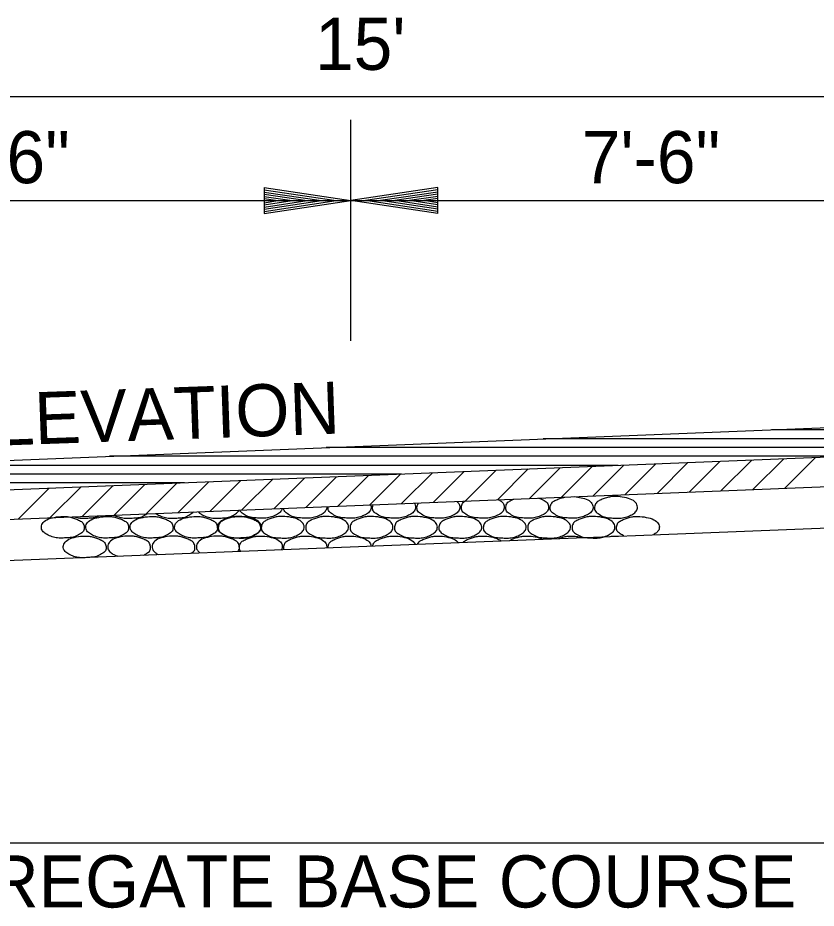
# Model space of a CAD drawing. Extents: x 1955768 to 1955917, y 566446 to 566546.
# Drawn here: x 1955835.83 to 1955845.04, y 566460.98 to 566471.25 of the extents above; entities that cross this region are included whole.
import ezdxf

# ---------------------------------------------------------------- set-up
doc = ezdxf.new("R2010")
doc.units = 0
doc.layers.add('R_Border', color=7, linetype='Continuous')
doc.layers.add('R_Grid', color=7, linetype='Continuous')

msp = doc.modelspace()

# ---------------------------------------------------------------- linework, layer by layer
at = {"layer": 'R_Border'}
for p, q in [((1955826.173, 566465.764), (1955847.173, 566466.604)), ((1955826.087, 566465.42), (1955847.339, 566466.271)), ((1955831.826, 566465.309), (1955847.506, 566465.937)), ((1955820.673, 566464.389), (1955847.173, 566465.449))]:
    msp.add_line(p, q, dxfattribs=at)
at = {"layer": 'R_Grid'}
for p, q in [((1955847.173, 566470.336), (1955832.173, 566470.336)), ((1955839.673, 566467.522), (1955839.673, 566470.069)), ((1955838.671, 566469.289), (1955839.671, 566469.139)), ((1955838.671, 566469.289), (1955838.671, 566468.989)), ((1955838.671, 566469.264), (1955839.504, 566469.139)), ((1955838.671, 566469.238), (1955839.332, 566469.139)), ((1955840.673, 566469.289), (1955839.673, 566469.139)), ((1955840.673, 566469.264), (1955839.84, 566469.139)), ((1955840.673, 566469.238), (1955840.012, 566469.139)), ((1955840.673, 566468.989), (1955840.673, 566469.289)), ((1955832.173, 566469.139), (1955839.673, 566469.139)), ((1955838.671, 566469.213), (1955839.166, 566469.139)), ((1955838.671, 566469.187), (1955838.996, 566469.139)), ((1955838.671, 566469.162), (1955838.829, 566469.139)), ((1955838.671, 566468.989), (1955839.671, 566469.139)), ((1955838.671, 566469.09), (1955838.996, 566469.139)), ((1955838.671, 566469.039), (1955839.332, 566469.139)), ((1955838.671, 566469.014), (1955839.504, 566469.139)), ((1955838.671, 566469.064), (1955839.166, 566469.139)), ((1955838.671, 566469.115), (1955838.829, 566469.139)), ((1955839.673, 566469.139), (1955847.173, 566469.139)), ((1955840.673, 566468.989), (1955839.673, 566469.139)), ((1955840.673, 566469.014), (1955839.84, 566469.139)), ((1955840.673, 566469.039), (1955840.012, 566469.139)), ((1955840.673, 566469.213), (1955840.178, 566469.139)), ((1955840.673, 566469.064), (1955840.178, 566469.139)), ((1955840.673, 566469.188), (1955840.348, 566469.139)), ((1955840.673, 566469.09), (1955840.348, 566469.139)), ((1955840.673, 566469.162), (1955840.515, 566469.139)), ((1955840.673, 566469.115), (1955840.515, 566469.139)), ((1955851.239, 566466.498), (1955844.523, 566466.498)), ((1955850.532, 566466.393), (1955841.888, 566466.393)), ((1955847.904, 566466.293), (1955839.388, 566466.293)), ((1955845.395, 566466.193), (1955836.888, 566466.193)), ((1955844.294, 566466.149), (1955843.94, 566465.794)), ((1955844.663, 566466.163), (1955844.308, 566465.809)), ((1955845.031, 566466.178), (1955844.677, 566465.824)), ((1955842.754, 566466.087), (1955834.247, 566466.087)), ((1955841.716, 566466.046), (1955841.362, 566465.691)), ((1955842.085, 566466.06), (1955841.73, 566465.706)), ((1955842.453, 566466.075), (1955842.099, 566465.721)), ((1955842.821, 566466.09), (1955842.467, 566465.736)), ((1955843.19, 566466.105), (1955842.835, 566465.75)), ((1955843.558, 566466.119), (1955843.204, 566465.765)), ((1955843.926, 566466.134), (1955843.572, 566465.78)), ((1955840.254, 566465.987), (1955831.747, 566465.987)), ((1955839.138, 566465.942), (1955838.784, 566465.588)), ((1955839.507, 566465.957), (1955839.152, 566465.603)), ((1955839.875, 566465.972), (1955839.521, 566465.618)), ((1955840.243, 566465.987), (1955839.889, 566465.632)), ((1955840.612, 566466.001), (1955840.257, 566465.647)), ((1955840.98, 566466.016), (1955840.626, 566465.662)), ((1955841.348, 566466.031), (1955840.994, 566465.677)), ((1955837.754, 566465.887), (1955829.247, 566465.887)), ((1955836.56, 566465.839), (1955836.206, 566465.485)), ((1955836.929, 566465.854), (1955836.574, 566465.5)), ((1955837.297, 566465.869), (1955836.943, 566465.515)), ((1955837.665, 566465.884), (1955837.311, 566465.529)), ((1955838.034, 566465.898), (1955837.679, 566465.544)), ((1955838.402, 566465.913), (1955838.048, 566465.559)), ((1955838.77, 566465.928), (1955838.416, 566465.574)), ((1955836.192, 566465.825), (1955835.838, 566465.47)), ((1955847.173, 566461.733), (1955832.173, 566461.733))]:
    msp.add_line(p, q, dxfattribs=at)
for points, degree in [([(1955842.256, 566465.727), (1955842.273, 566465.725), (1955842.328, 566465.716), (1955842.408, 566465.695), (1955842.459, 566465.648), (1955842.47, 566465.593), (1955842.446, 566465.549), (1955842.402, 566465.518), (1955842.342, 566465.493), (1955842.277, 566465.478), (1955842.211, 566465.478), (1955842.15, 566465.483), (1955842.082, 566465.488), (1955842.021, 566465.524), (1955841.972, 566465.556), (1955841.967, 566465.607), (1955841.984, 566465.658), (1955842.023, 566465.682), (1955842.071, 566465.703), (1955842.109, 566465.715), (1955842.134, 566465.721), (1955842.139, 566465.722)], 3), ([(1955842.731, 566465.728), (1955842.76, 566465.729), (1955842.827, 566465.72), (1955842.92, 566465.695), (1955842.971, 566465.648), (1955842.982, 566465.593), (1955842.958, 566465.549), (1955842.914, 566465.518), (1955842.854, 566465.493), (1955842.789, 566465.478), (1955842.723, 566465.478), (1955842.662, 566465.483), (1955842.594, 566465.488), (1955842.533, 566465.524), (1955842.484, 566465.556), (1955842.479, 566465.607), (1955842.496, 566465.658), (1955842.535, 566465.682), (1955842.583, 566465.703), (1955842.629, 566465.717), (1955842.68, 566465.729), (1955842.712, 566465.73), (1955842.731, 566465.728)], 3), ([(1955839.901, 566465.632), (1955839.904, 566465.623), (1955839.91, 566465.593), (1955839.886, 566465.549), (1955839.842, 566465.518), (1955839.782, 566465.493), (1955839.717, 566465.478), (1955839.651, 566465.478), (1955839.59, 566465.483), (1955839.522, 566465.488), (1955839.461, 566465.524), (1955839.412, 566465.556), (1955839.409, 566465.594), (1955839.411, 566465.609), (1955839.411, 566465.613)], 3), ([(1955840.401, 566465.653), (1955840.406, 566465.647), (1955840.414, 566465.632), (1955840.422, 566465.593), (1955840.398, 566465.549), (1955840.354, 566465.518), (1955840.294, 566465.493), (1955840.229, 566465.478), (1955840.163, 566465.478), (1955840.102, 566465.483), (1955840.034, 566465.488), (1955839.973, 566465.524), (1955839.924, 566465.556), (1955839.92, 566465.6), (1955839.925, 566465.624), (1955839.929, 566465.634)], 3), ([(1955840.894, 566465.672), (1955840.907, 566465.662), (1955840.924, 566465.642), (1955840.934, 566465.593), (1955840.91, 566465.549), (1955840.866, 566465.518), (1955840.806, 566465.493), (1955840.741, 566465.478), (1955840.675, 566465.478), (1955840.614, 566465.483), (1955840.546, 566465.488), (1955840.485, 566465.524), (1955840.436, 566465.556), (1955840.431, 566465.607), (1955840.442, 566465.64), (1955840.452, 566465.654), (1955840.453, 566465.655)], 3), ([(1955841.374, 566465.691), (1955841.379, 566465.689), (1955841.406, 566465.675), (1955841.435, 566465.648), (1955841.446, 566465.593), (1955841.422, 566465.549), (1955841.378, 566465.518), (1955841.318, 566465.493), (1955841.253, 566465.478), (1955841.187, 566465.478), (1955841.126, 566465.483), (1955841.058, 566465.488), (1955840.997, 566465.524), (1955840.948, 566465.556), (1955840.943, 566465.607), (1955840.958, 566465.653), (1955840.98, 566465.67), (1955840.991, 566465.676)], 3), ([(1955841.835, 566465.71), (1955841.859, 566465.703), (1955841.905, 566465.686), (1955841.947, 566465.648), (1955841.958, 566465.593), (1955841.934, 566465.549), (1955841.89, 566465.518), (1955841.83, 566465.493), (1955841.765, 566465.478), (1955841.699, 566465.478), (1955841.638, 566465.483), (1955841.57, 566465.488), (1955841.509, 566465.524), (1955841.46, 566465.556), (1955841.455, 566465.607), (1955841.472, 566465.658), (1955841.51, 566465.681), (1955841.538, 566465.694), (1955841.55, 566465.698)], 3), ([(1955836.942, 566465.514), (1955836.956, 566465.508), (1955836.997, 566465.491), (1955837.054, 566465.478), (1955837.121, 566465.478), (1955837.182, 566465.483), (1955837.25, 566465.488), (1955837.294, 566465.514), (1955837.315, 566465.527), (1955837.318, 566465.529)], 3), ([(1955837.421, 566465.533), (1955837.426, 566465.53), (1955837.449, 566465.515), (1955837.502, 566465.493), (1955837.566, 566465.478), (1955837.633, 566465.478), (1955837.694, 566465.483), (1955837.762, 566465.488), (1955837.816, 566465.52), (1955837.847, 566465.54), (1955837.857, 566465.551)], 3), ([(1955837.912, 566465.553), (1955837.914, 566465.551), (1955837.924, 566465.539), (1955837.954, 566465.518), (1955838.014, 566465.493), (1955838.078, 566465.478), (1955838.145, 566465.478), (1955838.206, 566465.483), (1955838.274, 566465.488), (1955838.335, 566465.524), (1955838.374, 566465.55), (1955838.382, 566465.571), (1955838.383, 566465.572)], 3), ([(1955838.88, 566465.592), (1955838.876, 566465.575), (1955838.859, 566465.547), (1955838.818, 566465.518), (1955838.758, 566465.493), (1955838.693, 566465.478), (1955838.627, 566465.478), (1955838.566, 566465.483), (1955838.498, 566465.488), (1955838.437, 566465.524), (1955838.398, 566465.55), (1955838.389, 566465.571), (1955838.389, 566465.572)], 3), ([(1955839.393, 566465.612), (1955839.394, 566465.609), (1955839.394, 566465.586), (1955839.374, 566465.549), (1955839.33, 566465.518), (1955839.27, 566465.493), (1955839.205, 566465.478), (1955839.139, 566465.478), (1955839.078, 566465.483), (1955839.01, 566465.488), (1955838.949, 566465.524), (1955838.903, 566465.554), (1955838.898, 566465.584), (1955838.898, 566465.592)], 3), ([(1955836.349, 566465.499), (1955836.319, 566465.499), (1955836.252, 566465.491), (1955836.159, 566465.465), (1955836.108, 566465.419), (1955836.097, 566465.364), (1955836.121, 566465.32), (1955836.166, 566465.289), (1955836.225, 566465.264), (1955836.29, 566465.248), (1955836.356, 566465.249), (1955836.417, 566465.254), (1955836.486, 566465.259), (1955836.546, 566465.295), (1955836.595, 566465.327), (1955836.6, 566465.378), (1955836.584, 566465.428), (1955836.545, 566465.452), (1955836.497, 566465.473), (1955836.45, 566465.488), (1955836.399, 566465.499), (1955836.367, 566465.501), (1955836.349, 566465.499)], 3), ([(1955836.477, 566465.496), (1955836.503, 566465.487), (1955836.544, 566465.478), (1955836.609, 566465.478), (1955836.67, 566465.483), (1955836.728, 566465.487), (1955836.76, 566465.502), (1955836.769, 566465.507)], 3), ([(1955836.861, 566465.499), (1955836.831, 566465.499), (1955836.764, 566465.491), (1955836.671, 566465.465), (1955836.62, 566465.419), (1955836.609, 566465.364), (1955836.633, 566465.32), (1955836.678, 566465.289), (1955836.737, 566465.264), (1955836.802, 566465.248), (1955836.868, 566465.249), (1955836.929, 566465.254), (1955836.998, 566465.259), (1955837.058, 566465.295), (1955837.107, 566465.327), (1955837.112, 566465.378), (1955837.096, 566465.428), (1955837.057, 566465.452), (1955837.009, 566465.473), (1955836.962, 566465.488), (1955836.911, 566465.499), (1955836.879, 566465.501), (1955836.861, 566465.499)], 3), ([(1955837.373, 566465.499), (1955837.343, 566465.499), (1955837.276, 566465.491), (1955837.183, 566465.465), (1955837.132, 566465.419), (1955837.121, 566465.364), (1955837.145, 566465.32), (1955837.19, 566465.289), (1955837.249, 566465.264), (1955837.314, 566465.248), (1955837.38, 566465.249), (1955837.441, 566465.254), (1955837.51, 566465.259), (1955837.57, 566465.295), (1955837.619, 566465.327), (1955837.624, 566465.378), (1955837.608, 566465.428), (1955837.569, 566465.452), (1955837.521, 566465.473), (1955837.474, 566465.488), (1955837.423, 566465.499), (1955837.391, 566465.501), (1955837.373, 566465.499)], 3), ([(1955837.885, 566465.499), (1955837.855, 566465.499), (1955837.788, 566465.491), (1955837.695, 566465.465), (1955837.644, 566465.419), (1955837.633, 566465.364), (1955837.657, 566465.32), (1955837.702, 566465.289), (1955837.761, 566465.264), (1955837.826, 566465.248), (1955837.892, 566465.249), (1955837.953, 566465.254), (1955838.022, 566465.259), (1955838.082, 566465.295), (1955838.131, 566465.327), (1955838.136, 566465.378), (1955838.12, 566465.428), (1955838.081, 566465.452), (1955838.033, 566465.473), (1955837.986, 566465.488), (1955837.935, 566465.499), (1955837.903, 566465.501), (1955837.885, 566465.499)], 3), ([(1955838.38, 566465.499), (1955838.351, 566465.499), (1955838.284, 566465.491), (1955838.191, 566465.465), (1955838.14, 566465.419), (1955838.129, 566465.364), (1955838.153, 566465.32), (1955838.197, 566465.289), (1955838.257, 566465.264), (1955838.322, 566465.248), (1955838.388, 566465.249), (1955838.449, 566465.254), (1955838.517, 566465.259), (1955838.578, 566465.295), (1955838.627, 566465.327), (1955838.632, 566465.378), (1955838.615, 566465.428), (1955838.576, 566465.452), (1955838.528, 566465.473), (1955838.482, 566465.488), (1955838.431, 566465.499), (1955838.399, 566465.501), (1955838.38, 566465.499)], 3), ([(1955838.391, 566465.499), (1955838.421, 566465.499), (1955838.488, 566465.491), (1955838.581, 566465.465), (1955838.632, 566465.419), (1955838.643, 566465.364), (1955838.619, 566465.32), (1955838.575, 566465.289), (1955838.515, 566465.264), (1955838.45, 566465.248), (1955838.384, 566465.249), (1955838.323, 566465.254), (1955838.254, 566465.259), (1955838.194, 566465.295), (1955838.145, 566465.327), (1955838.14, 566465.378), (1955838.157, 566465.428), (1955838.196, 566465.452), (1955838.243, 566465.473), (1955838.29, 566465.488), (1955838.341, 566465.499), (1955838.373, 566465.501), (1955838.391, 566465.499)], 3), ([(1955838.887, 566465.499), (1955838.916, 566465.499), (1955838.984, 566465.491), (1955839.076, 566465.465), (1955839.127, 566465.419), (1955839.139, 566465.364), (1955839.114, 566465.32), (1955839.07, 566465.289), (1955839.011, 566465.264), (1955838.946, 566465.248), (1955838.88, 566465.249), (1955838.819, 566465.254), (1955838.75, 566465.259), (1955838.689, 566465.295), (1955838.641, 566465.327), (1955838.636, 566465.378), (1955838.652, 566465.428), (1955838.691, 566465.452), (1955838.739, 566465.473), (1955838.785, 566465.488), (1955838.836, 566465.499), (1955838.869, 566465.501), (1955838.887, 566465.499)], 3), ([(1955839.399, 566465.499), (1955839.428, 566465.499), (1955839.496, 566465.491), (1955839.588, 566465.465), (1955839.639, 566465.419), (1955839.651, 566465.364), (1955839.626, 566465.32), (1955839.582, 566465.289), (1955839.523, 566465.264), (1955839.458, 566465.248), (1955839.392, 566465.249), (1955839.331, 566465.254), (1955839.262, 566465.259), (1955839.201, 566465.295), (1955839.153, 566465.327), (1955839.148, 566465.378), (1955839.164, 566465.428), (1955839.203, 566465.452), (1955839.251, 566465.473), (1955839.297, 566465.488), (1955839.348, 566465.499), (1955839.381, 566465.501), (1955839.399, 566465.499)], 3), ([(1955839.911, 566465.499), (1955839.94, 566465.499), (1955840.008, 566465.491), (1955840.1, 566465.465), (1955840.151, 566465.419), (1955840.163, 566465.364), (1955840.138, 566465.32), (1955840.094, 566465.289), (1955840.035, 566465.264), (1955839.97, 566465.248), (1955839.904, 566465.249), (1955839.843, 566465.254), (1955839.774, 566465.259), (1955839.713, 566465.295), (1955839.665, 566465.327), (1955839.66, 566465.378), (1955839.676, 566465.428), (1955839.715, 566465.452), (1955839.763, 566465.473), (1955839.809, 566465.488), (1955839.86, 566465.499), (1955839.893, 566465.501), (1955839.911, 566465.499)], 3), ([(1955840.423, 566465.499), (1955840.452, 566465.499), (1955840.52, 566465.491), (1955840.612, 566465.465), (1955840.663, 566465.419), (1955840.675, 566465.364), (1955840.65, 566465.32), (1955840.606, 566465.289), (1955840.547, 566465.264), (1955840.482, 566465.248), (1955840.416, 566465.249), (1955840.355, 566465.254), (1955840.286, 566465.259), (1955840.225, 566465.295), (1955840.177, 566465.327), (1955840.172, 566465.378), (1955840.188, 566465.428), (1955840.227, 566465.452), (1955840.275, 566465.473), (1955840.321, 566465.488), (1955840.372, 566465.499), (1955840.405, 566465.501), (1955840.423, 566465.499)], 3), ([(1955840.935, 566465.499), (1955840.964, 566465.499), (1955841.032, 566465.491), (1955841.124, 566465.465), (1955841.175, 566465.419), (1955841.187, 566465.364), (1955841.162, 566465.32), (1955841.118, 566465.289), (1955841.059, 566465.264), (1955840.994, 566465.248), (1955840.928, 566465.249), (1955840.867, 566465.254), (1955840.798, 566465.259), (1955840.737, 566465.295), (1955840.689, 566465.327), (1955840.684, 566465.378), (1955840.7, 566465.428), (1955840.739, 566465.452), (1955840.787, 566465.473), (1955840.833, 566465.488), (1955840.884, 566465.499), (1955840.917, 566465.501), (1955840.935, 566465.499)], 3), ([(1955841.447, 566465.499), (1955841.476, 566465.499), (1955841.544, 566465.491), (1955841.636, 566465.465), (1955841.687, 566465.419), (1955841.699, 566465.364), (1955841.674, 566465.32), (1955841.63, 566465.289), (1955841.571, 566465.264), (1955841.506, 566465.248), (1955841.44, 566465.249), (1955841.379, 566465.254), (1955841.31, 566465.259), (1955841.249, 566465.295), (1955841.201, 566465.327), (1955841.196, 566465.378), (1955841.212, 566465.428), (1955841.251, 566465.452), (1955841.299, 566465.473), (1955841.345, 566465.488), (1955841.396, 566465.499), (1955841.429, 566465.501), (1955841.447, 566465.499)], 3), ([(1955841.959, 566465.499), (1955841.988, 566465.499), (1955842.056, 566465.491), (1955842.148, 566465.465), (1955842.199, 566465.419), (1955842.211, 566465.364), (1955842.186, 566465.32), (1955842.142, 566465.289), (1955842.083, 566465.264), (1955842.018, 566465.248), (1955841.952, 566465.249), (1955841.891, 566465.254), (1955841.822, 566465.259), (1955841.761, 566465.295), (1955841.713, 566465.327), (1955841.708, 566465.378), (1955841.724, 566465.428), (1955841.763, 566465.452), (1955841.811, 566465.473), (1955841.857, 566465.488), (1955841.908, 566465.499), (1955841.941, 566465.501), (1955841.959, 566465.499)], 3), ([(1955842.471, 566465.499), (1955842.5, 566465.499), (1955842.568, 566465.491), (1955842.66, 566465.465), (1955842.711, 566465.419), (1955842.723, 566465.364), (1955842.698, 566465.32), (1955842.654, 566465.289), (1955842.595, 566465.264), (1955842.53, 566465.248), (1955842.464, 566465.249), (1955842.403, 566465.254), (1955842.334, 566465.259), (1955842.273, 566465.295), (1955842.225, 566465.327), (1955842.22, 566465.378), (1955842.236, 566465.428), (1955842.275, 566465.452), (1955842.323, 566465.473), (1955842.369, 566465.488), (1955842.42, 566465.499), (1955842.453, 566465.501), (1955842.471, 566465.499)], 3), ([(1955842.821, 566465.275), (1955842.81, 566465.28), (1955842.778, 566465.299), (1955842.737, 566465.327), (1955842.732, 566465.378), (1955842.748, 566465.428), (1955842.787, 566465.452), (1955842.835, 566465.473), (1955842.881, 566465.488), (1955842.932, 566465.499), (1955842.965, 566465.501), (1955842.983, 566465.499)], 3), ([(1955842.983, 566465.499), (1955843.012, 566465.499), (1955843.08, 566465.491), (1955843.172, 566465.465), (1955843.223, 566465.419), (1955843.235, 566465.364), (1955843.21, 566465.32), (1955843.18, 566465.299), (1955843.165, 566465.291), (1955843.161, 566465.288)], 3), ([(1955836.601, 566465.273), (1955836.572, 566465.273), (1955836.504, 566465.264), (1955836.412, 566465.239), (1955836.361, 566465.193), (1955836.35, 566465.138), (1955836.374, 566465.093), (1955836.418, 566465.063), (1955836.478, 566465.037), (1955836.542, 566465.022), (1955836.609, 566465.023), (1955836.67, 566465.028), (1955836.738, 566465.033), (1955836.799, 566465.069), (1955836.848, 566465.101), (1955836.853, 566465.152), (1955836.836, 566465.202), (1955836.797, 566465.226), (1955836.749, 566465.247), (1955836.703, 566465.262), (1955836.652, 566465.273), (1955836.62, 566465.274), (1955836.601, 566465.273)], 3), ([(1955837.113, 566465.273), (1955837.084, 566465.273), (1955837.016, 566465.264), (1955836.924, 566465.239), (1955836.873, 566465.193), (1955836.862, 566465.138), (1955836.886, 566465.093), (1955836.93, 566465.063), (1955836.963, 566465.049), (1955836.984, 566465.041), (1955836.985, 566465.041)], 3), ([(1955837.285, 566465.053), (1955837.293, 566465.058), (1955837.321, 566465.075), (1955837.36, 566465.101), (1955837.365, 566465.152), (1955837.348, 566465.202), (1955837.309, 566465.226), (1955837.261, 566465.247), (1955837.215, 566465.262), (1955837.164, 566465.273), (1955837.132, 566465.274), (1955837.113, 566465.273)], 3), ([(1955837.625, 566465.273), (1955837.596, 566465.273), (1955837.528, 566465.264), (1955837.436, 566465.239), (1955837.385, 566465.193), (1955837.374, 566465.138), (1955837.398, 566465.093), (1955837.429, 566465.072), (1955837.446, 566465.063), (1955837.451, 566465.06)], 3), ([(1955837.832, 566465.075), (1955837.848, 566465.086), (1955837.872, 566465.105), (1955837.877, 566465.152), (1955837.86, 566465.202), (1955837.821, 566465.226), (1955837.773, 566465.247), (1955837.727, 566465.262), (1955837.676, 566465.273), (1955837.644, 566465.274), (1955837.625, 566465.273)], 3), ([(1955838.137, 566465.273), (1955838.108, 566465.273), (1955838.04, 566465.264), (1955837.948, 566465.239), (1955837.897, 566465.193), (1955837.886, 566465.138), (1955837.906, 566465.1), (1955837.926, 566465.083), (1955837.931, 566465.079)], 3), ([(1955838.371, 566465.097), (1955838.375, 566465.102), (1955838.385, 566465.116), (1955838.389, 566465.152), (1955838.372, 566465.202), (1955838.333, 566465.226), (1955838.285, 566465.247), (1955838.239, 566465.262), (1955838.188, 566465.273), (1955838.156, 566465.274), (1955838.137, 566465.273)], 3), ([(1955838.4, 566465.098), (1955838.396, 566465.103), (1955838.387, 566465.117), (1955838.383, 566465.152), (1955838.4, 566465.202), (1955838.439, 566465.226), (1955838.487, 566465.247), (1955838.533, 566465.262), (1955838.584, 566465.273), (1955838.616, 566465.274), (1955838.635, 566465.273)], 3), ([(1955838.635, 566465.273), (1955838.664, 566465.273), (1955838.731, 566465.264), (1955838.824, 566465.239), (1955838.875, 566465.193), (1955838.884, 566465.148), (1955838.878, 566465.127), (1955838.873, 566465.117)], 3), ([(1955838.901, 566465.118), (1955838.898, 566465.127), (1955838.896, 566465.154), (1955838.912, 566465.202), (1955838.951, 566465.226), (1955838.999, 566465.247), (1955839.045, 566465.262), (1955839.096, 566465.273), (1955839.128, 566465.274), (1955839.147, 566465.273)], 3), ([(1955839.147, 566465.273), (1955839.176, 566465.273), (1955839.243, 566465.264), (1955839.336, 566465.239), (1955839.387, 566465.193), (1955839.395, 566465.155), (1955839.393, 566465.141), (1955839.392, 566465.138)], 3), ([(1955839.41, 566465.138), (1955839.41, 566465.141), (1955839.41, 566465.161), (1955839.424, 566465.202), (1955839.463, 566465.226), (1955839.511, 566465.247), (1955839.557, 566465.262), (1955839.608, 566465.273), (1955839.64, 566465.274), (1955839.659, 566465.273)], 3), ([(1955839.659, 566465.273), (1955839.688, 566465.273), (1955839.755, 566465.264), (1955839.848, 566465.239), (1955839.896, 566465.195), (1955839.904, 566465.165), (1955839.905, 566465.158)], 3), ([(1955839.924, 566465.159), (1955839.926, 566465.173), (1955839.939, 566465.204), (1955839.975, 566465.226), (1955840.023, 566465.247), (1955840.069, 566465.262), (1955840.12, 566465.273), (1955840.152, 566465.274), (1955840.171, 566465.273)], 3), ([(1955840.171, 566465.273), (1955840.2, 566465.273), (1955840.267, 566465.264), (1955840.36, 566465.239), (1955840.403, 566465.2), (1955840.412, 566465.178)], 3), ([(1955840.442, 566465.18), (1955840.444, 566465.186), (1955840.456, 566465.207), (1955840.487, 566465.226), (1955840.535, 566465.247), (1955840.581, 566465.262), (1955840.632, 566465.273), (1955840.664, 566465.274), (1955840.683, 566465.273)], 3), ([(1955840.683, 566465.273), (1955840.712, 566465.273), (1955840.779, 566465.264), (1955840.863, 566465.241), (1955840.903, 566465.21), (1955840.912, 566465.198)], 3), ([(1955840.966, 566465.201), (1955840.976, 566465.212), (1955841, 566465.227), (1955841.047, 566465.247), (1955841.093, 566465.262), (1955841.144, 566465.273), (1955841.176, 566465.274), (1955841.195, 566465.273)], 3), ([(1955841.195, 566465.273), (1955841.224, 566465.273), (1955841.291, 566465.264), (1955841.365, 566465.244), (1955841.399, 566465.221), (1955841.404, 566465.218)], 3), ([(1955841.506, 566465.222), (1955841.508, 566465.224), (1955841.523, 566465.232), (1955841.559, 566465.247), (1955841.605, 566465.262), (1955841.656, 566465.273), (1955841.688, 566465.274), (1955841.707, 566465.273)], 3), ([(1955841.707, 566465.273), (1955841.736, 566465.273), (1955841.796, 566465.265), (1955841.857, 566465.25), (1955841.883, 566465.237)], 3), ([(1955842.067, 566465.245), (1955842.086, 566465.252), (1955842.117, 566465.262), (1955842.168, 566465.273), (1955842.2, 566465.274), (1955842.219, 566465.273)], 3), ([(1955842.219, 566465.273), (1955842.248, 566465.273), (1955842.29, 566465.268), (1955842.331, 566465.259), (1955842.342, 566465.256)], 3), ([(1955842.66, 566465.268), (1955842.665, 566465.269), (1955842.688, 566465.273), (1955842.712, 566465.274), (1955842.731, 566465.273)], 3), ([(1955842.731, 566465.273), (1955842.738, 566465.273), (1955842.746, 566465.273), (1955842.754, 566465.272)], 2)]:
    msp.add_open_spline(points, degree=degree, dxfattribs=at)

# ---------------------------------------------------------------- texts
at = {"layer": 'R_Border'}
for s, p in [("15'", (1955839.257, 566470.646)), ('7\'-6"', (1955834.834, 566469.34)), ('7\'-6"', (1955842.334, 566469.34)), ('AGGREGATE BASE COURSE', (1955833.709, 566460.992))]:
    msp.add_text(s, height=0.6, dxfattribs=at).set_placement(p)
msp.add_text('SUPERELEVATION', height=0.6, rotation=2.0327, dxfattribs=at).set_placement((1955832.289, 566466.197))

doc.saveas('drawing.dxf')
